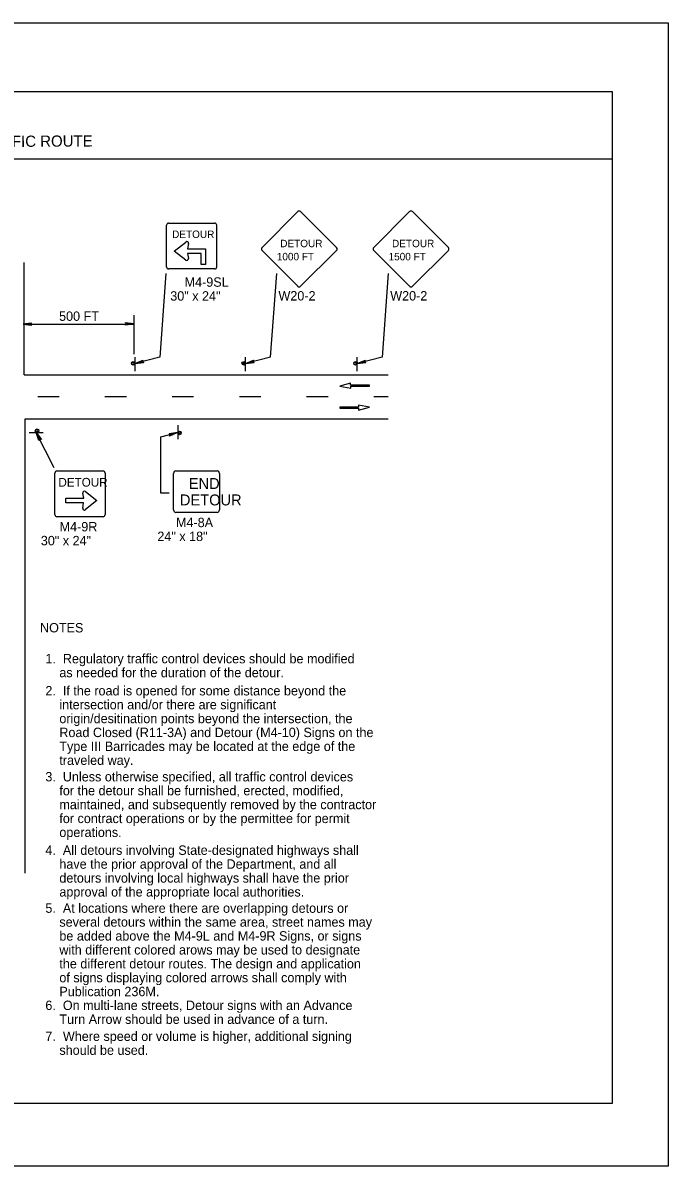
# Model space of a CAD drawing. Extents: x -14145 to -13662, y 30244 to 30661.
# Drawn here: x -13873.57 to -13859.17, y 30262.81 to 30288.31 of the extents above; entities that cross this region are included whole.
import ezdxf

# ---------------------------------------------------------------- set-up
doc = ezdxf.new("R2010")
doc.units = 0
for name, color, linetype in [('1', 7, 'Continuous'), ('10', 7, 'Continuous'), ('2', 7, 'Continuous'), ('4', 7, 'Continuous'), ('61', 7, 'Continuous')]:
    doc.layers.add(name, color=color, linetype=linetype)

msp = doc.modelspace()

# ---------------------------------------------------------------- linework, layer by layer
at = {"layer": '1'}
for p, q in [((-13867.44, 30284.096), (-13868.235, 30283.293)), ((-13866.571, 30283.293), (-13867.374, 30284.096)), ((-13864.946, 30284.096), (-13865.741, 30283.293)), ((-13864.077, 30283.293), (-13864.88, 30284.096)), ((-13870.324, 30283.842), (-13869.291, 30283.842)), ((-13870.367, 30282.866), (-13870.367, 30283.792)), ((-13869.248, 30283.792), (-13869.248, 30282.866)), ((-13870.193, 30283.215), (-13869.936, 30283.418)), ((-13869.875, 30283.382), (-13869.895, 30283.268)), ((-13869.939, 30283.015), (-13870.193, 30283.215)), ((-13869.896, 30283.161), (-13869.877, 30283.049)), ((-13869.597, 30283.161), (-13869.896, 30283.161)), ((-13869.895, 30283.268), (-13869.495, 30283.268)), ((-13869.597, 30282.915), (-13869.597, 30283.163)), ((-13869.495, 30283.268), (-13869.495, 30282.915)), ((-13868.235, 30283.227), (-13867.44, 30282.432)), ((-13867.374, 30282.432), (-13866.571, 30283.227)), ((-13865.741, 30283.227), (-13864.946, 30282.432)), ((-13864.88, 30282.432), (-13864.077, 30283.227)), ((-13873.543, 30280.459), (-13873.543, 30282.96)), ((-13869.291, 30282.817), (-13870.324, 30282.817)), ((-13869.495, 30282.915), (-13869.597, 30282.915)), ((-13870.38, 30282.718), (-13870.517, 30280.847)), ((-13867.914, 30282.718), (-13868.051, 30280.847)), ((-13865.42, 30282.718), (-13865.557, 30280.847)), ((-13871.099, 30281.789), (-13871.099, 30280.915)), ((-13873.565, 30281.585), (-13871.099, 30281.585)), ((-13871.069, 30280.54), (-13871.069, 30280.852)), ((-13871.069, 30280.54), (-13871.069, 30280.852)), ((-13870.516, 30280.847), (-13871.063, 30280.707)), ((-13868.603, 30280.54), (-13868.603, 30280.852)), ((-13868.603, 30280.54), (-13868.603, 30280.852)), ((-13868.05, 30280.847), (-13868.597, 30280.707)), ((-13866.109, 30280.54), (-13866.109, 30280.852)), ((-13866.109, 30280.54), (-13866.109, 30280.852)), ((-13865.556, 30280.847), (-13866.103, 30280.707)), ((-13873.543, 30280.459), (-13865.423, 30280.459)), ((-13866.258, 30280.271), (-13866.499, 30280.205)), ((-13866.258, 30280.226), (-13866.258, 30280.271)), ((-13866.499, 30280.205), (-13866.255, 30280.159)), ((-13865.841, 30280.226), (-13866.258, 30280.226)), ((-13866.255, 30280.159), (-13866.255, 30280.204)), ((-13866.255, 30280.204), (-13865.841, 30280.204)), ((-13865.841, 30280.204), (-13865.841, 30280.226)), ((-13872.761, 30279.968), (-13873.241, 30279.968)), ((-13871.261, 30279.968), (-13871.741, 30279.968)), ((-13869.761, 30279.968), (-13870.241, 30279.968)), ((-13868.261, 30279.968), (-13868.741, 30279.968)), ((-13866.761, 30279.968), (-13867.241, 30279.968)), ((-13866.085, 30279.735), (-13866.499, 30279.735)), ((-13866.499, 30279.735), (-13866.499, 30279.713)), ((-13865.841, 30279.734), (-13866.085, 30279.78)), ((-13866.085, 30279.78), (-13866.085, 30279.735)), ((-13866.083, 30279.668), (-13865.841, 30279.734)), ((-13865.423, 30279.968), (-13865.741, 30279.968)), ((-13873.52, 30279.475), (-13865.423, 30279.475)), ((-13873.52, 30269.341), (-13873.52, 30279.475)), ((-13866.499, 30279.713), (-13866.083, 30279.713)), ((-13866.083, 30279.713), (-13866.083, 30279.668)), ((-13870.117, 30279.334), (-13870.117, 30279.022)), ((-13870.117, 30279.334), (-13870.117, 30279.022)), ((-13870.117, 30279.334), (-13870.117, 30279.022)), ((-13870.117, 30279.334), (-13870.117, 30279.022)), ((-13870.117, 30279.334), (-13870.117, 30279.022)), ((-13870.117, 30279.334), (-13870.117, 30279.022)), ((-13873.428, 30279.17), (-13873.116, 30279.17)), ((-13873.428, 30279.17), (-13873.116, 30279.17)), ((-13873.428, 30279.17), (-13873.116, 30279.17)), ((-13873.428, 30279.17), (-13873.116, 30279.17)), ((-13873.428, 30279.17), (-13873.116, 30279.17)), ((-13873.428, 30279.17), (-13873.116, 30279.17)), ((-13872.876, 30278.384), (-13873.272, 30279.17)), ((-13870.498, 30279.072), (-13870.498, 30277.828)), ((-13870.497, 30279.071), (-13870.123, 30279.167)), ((-13872.856, 30277.34), (-13872.856, 30278.266)), ((-13872.813, 30278.316), (-13871.78, 30278.316)), ((-13871.737, 30278.266), (-13871.737, 30277.34)), ((-13870.21, 30277.447), (-13870.21, 30278.254)), ((-13870.16, 30278.314), (-13869.234, 30278.314)), ((-13869.185, 30278.254), (-13869.185, 30277.447)), ((-13872.616, 30277.6), (-13872.616, 30277.707)), ((-13872.616, 30277.707), (-13872.215, 30277.707)), ((-13872.215, 30277.707), (-13872.234, 30277.819)), ((-13872.172, 30277.853), (-13871.918, 30277.653)), ((-13870.498, 30277.828), (-13870.304, 30277.828)), ((-13872.216, 30277.6), (-13872.616, 30277.6)), ((-13872.236, 30277.486), (-13872.216, 30277.6)), ((-13871.918, 30277.653), (-13872.175, 30277.45)), ((-13871.78, 30277.291), (-13872.813, 30277.291)), ((-13869.234, 30277.386), (-13870.16, 30277.386))]:
    msp.add_line(p, q, dxfattribs=at)
for points in [[(-13873.385, 30281.561), (-13873.391, 30281.579), (-13873.565, 30281.585), (-13873.385, 30281.561), (-13873.379, 30281.555), (-13873.565, 30281.585), (-13873.391, 30281.591), (-13873.385, 30281.609), (-13873.565, 30281.585), (-13873.379, 30281.615), (-13873.385, 30281.609)], [(-13871.279, 30281.615), (-13871.273, 30281.603), (-13871.099, 30281.591), (-13871.279, 30281.615), (-13871.285, 30281.621), (-13871.099, 30281.591), (-13871.273, 30281.585), (-13871.279, 30281.573), (-13871.099, 30281.591), (-13871.285, 30281.561), (-13871.279, 30281.573)], [(-13870.883, 30280.731), (-13870.895, 30280.743), (-13871.063, 30280.707), (-13870.883, 30280.731), (-13870.877, 30280.725), (-13871.063, 30280.707), (-13870.901, 30280.761), (-13870.895, 30280.773), (-13871.063, 30280.707), (-13870.889, 30280.785), (-13870.895, 30280.773)], [(-13868.417, 30280.731), (-13868.429, 30280.743), (-13868.597, 30280.707), (-13868.417, 30280.731), (-13868.411, 30280.725), (-13868.597, 30280.707), (-13868.435, 30280.761), (-13868.429, 30280.773), (-13868.597, 30280.707), (-13868.423, 30280.785), (-13868.429, 30280.773)], [(-13865.923, 30280.731), (-13865.935, 30280.743), (-13866.103, 30280.707), (-13865.923, 30280.731), (-13865.917, 30280.725), (-13866.103, 30280.707), (-13865.941, 30280.761), (-13865.935, 30280.773), (-13866.103, 30280.707), (-13865.929, 30280.785), (-13865.935, 30280.773)], [(-13873.21, 30278.999), (-13873.201, 30279.014), (-13873.272, 30279.17), (-13873.21, 30278.999), (-13873.215, 30278.992), (-13873.272, 30279.17), (-13873.185, 30279.023), (-13873.172, 30279.02), (-13873.272, 30279.17), (-13873.159, 30279.017), (-13873.172, 30279.02)], [(-13873.21, 30278.999), (-13873.201, 30279.014), (-13873.272, 30279.17), (-13873.21, 30278.999), (-13873.215, 30278.992), (-13873.272, 30279.17), (-13873.185, 30279.023), (-13873.172, 30279.02), (-13873.272, 30279.17), (-13873.159, 30279.017), (-13873.172, 30279.02)], [(-13873.21, 30278.999), (-13873.201, 30279.014), (-13873.272, 30279.17), (-13873.21, 30278.999), (-13873.215, 30278.992), (-13873.272, 30279.17), (-13873.185, 30279.023), (-13873.172, 30279.02), (-13873.272, 30279.17), (-13873.159, 30279.017), (-13873.172, 30279.02)], [(-13870.303, 30279.143), (-13870.291, 30279.131), (-13870.123, 30279.167), (-13870.303, 30279.143), (-13870.309, 30279.149), (-13870.123, 30279.167), (-13870.285, 30279.113), (-13870.291, 30279.101), (-13870.123, 30279.167), (-13870.297, 30279.089), (-13870.291, 30279.101)]]:
    msp.add_lwpolyline(points, dxfattribs=at)
for centre in [(-13871.109, 30280.713), (-13868.643, 30280.713), (-13866.149, 30280.713), (-13873.254, 30279.211), (-13873.254, 30279.211), (-13873.254, 30279.211), (-13870.077, 30279.161), (-13870.077, 30279.161), (-13870.077, 30279.161)]:
    msp.add_circle(centre, 0.0408, dxfattribs=at)
for centre, radius, start, end in [((-13867.408, 30284.063), 0.0465, 45, 135), ((-13864.914, 30284.063), 0.0465, 45, 135), ((-13869.913, 30283.389), 0.038, 348.2476, 132.1543), ((-13868.203, 30283.261), 0.0465, 135, 225), ((-13866.605, 30283.26), 0.0465, 315, 45), ((-13865.709, 30283.261), 0.0465, 135, 225), ((-13864.111, 30283.26), 0.0465, 315, 45), ((-13869.915, 30283.045), 0.038, 229.8591, 10.5247), ((-13867.408, 30282.465), 0.0465, 225, 315), ((-13864.914, 30282.465), 0.0465, 225, 315), ((-13871.104, 30280.705), 0.0214, 9.521, 4.2501), ((-13868.638, 30280.705), 0.0214, 9.521, 4.2501), ((-13866.144, 30280.705), 0.0214, 9.521, 4.2501), ((-13873.262, 30279.206), 0.0214, 279.521, 274.2501), ((-13873.262, 30279.206), 0.0214, 279.521, 274.2501), ((-13873.262, 30279.206), 0.0214, 279.521, 274.2501), ((-13870.082, 30279.169), 0.0214, 189.521, 184.2501), ((-13870.082, 30279.169), 0.0214, 189.521, 184.2501), ((-13870.082, 30279.169), 0.0214, 189.521, 184.2501), ((-13872.198, 30277.823), 0.038, 49.8591, 190.5247), ((-13872.2, 30277.479), 0.038, 168.2476, 312.1543)]:
    msp.add_arc(centre, radius, start, end, dxfattribs=at)
for centre, major_axis, ratio, start_param, end_param in [((-13870.324, 30283.792), (0, -0.0492), 0.866667, 3.141593, 4.712389), ((-13869.29, 30283.792), (0, 0.0492), 0.866667, 4.712389, 6.283185), ((-13870.324, 30282.865), (0, -0.0492), 0.866667, 4.712389, 6.283185), ((-13869.29, 30282.865), (0, 0.0492), 0.866667, 3.141593, 4.712389), ((-13872.813, 30278.266), (0, -0.0492), 0.866667, 3.141593, 4.712389), ((-13871.78, 30278.266), (0, 0.0492), 0.866667, 4.712389, 6.283185), ((-13870.161, 30278.254), (0, -0.0602), 0.817773, 3.141593, 4.712389), ((-13869.235, 30278.254), (0, 0.0602), 0.817773, 4.712389, 6.283185), ((-13870.161, 30277.447), (0, -0.0602), 0.817773, 4.712389, 6.283185), ((-13869.235, 30277.447), (0, 0.0602), 0.817773, 3.141593, 4.712389), ((-13872.813, 30277.339), (0, -0.0492), 0.866667, 4.712389, 6.283185), ((-13871.78, 30277.339), (0, 0.0492), 0.866667, 3.141593, 4.712389)]:
    msp.add_ellipse(centre, major_axis=major_axis, ratio=ratio, start_param=start_param, end_param=end_param, dxfattribs=at)
at = {"layer": '10'}
for p, q in [((-13891.874, 30286.777), (-13860.422, 30286.777)), ((-13860.422, 30286.777), (-13860.422, 30264.207)), ((-13891.874, 30285.277), (-13860.422, 30285.277)), ((-13860.422, 30264.207), (-13891.874, 30264.207))]:
    msp.add_line(p, q, dxfattribs=at)
at = {"layer": '61'}
msp.add_lwpolyline([(-13892.174, 30288.307), (-13859.174, 30288.307), (-13859.174, 30262.807), (-13892.174, 30262.807)], close=True, dxfattribs=at)

# ---------------------------------------------------------------- texts
at = {"layer": '1'}
for s, height, p in [('DETOUR', 0.1669, (-13870.242, 30283.508)), ('DETOUR', 0.1669, (-13867.829, 30283.303)), ('DETOUR', 0.1669, (-13865.335, 30283.303)), ('1000 FT', 0.1669, (-13867.906, 30283.01)), ('1500 FT', 0.1669, (-13865.412, 30283.01)), ('DETOUR', 0.1941, (-13872.778, 30277.963)), ('END', 0.244, (-13869.87, 30277.91)), ('DETOUR', 0.244, (-13870.068, 30277.544))]:
    msp.add_text(s, height=height, dxfattribs=at).set_placement(p)
at = {"layer": '2'}
for s, p in [('M4-9SL', (-13869.963, 30282.421)), ('30" x 24"', (-13870.283, 30282.111)), ('W20-2', (-13867.869, 30282.114)), ('W20-2', (-13865.375, 30282.114)), ('500 FT', (-13872.764, 30281.66)), ('M4-9R', (-13872.752, 30276.964)), ('M4-8A', (-13870.155, 30277.059)), ('24" x 18"', (-13870.571, 30276.749)), ('30" x 24"', (-13873.171, 30276.654)), ('NOTES', (-13873.189, 30274.711)), ('1.  Regulatory traffic control devices should be modified ', (-13873.07, 30274.021)), ('    as needed for the duration of the detour.', (-13873.07, 30273.711)), ('2.  If the road is opened for some distance beyond the', (-13873.07, 30273.306)), ('    intersection and/or there are significant', (-13873.07, 30272.996)), ('    origin/desitination points beyond the intersection, the', (-13873.07, 30272.686)), ('    Road Closed (R11-3A) and Detour (M4-10) Signs on the', (-13873.07, 30272.376)), ('    Type III Barricades may be located at the edge of the', (-13873.07, 30272.066)), ('    traveled way.', (-13873.07, 30271.756)), ('3.  Unless otherwise specified, all traffic control devices', (-13873.07, 30271.388)), ('    for the detour shall be furnished, erected, modified,', (-13873.07, 30271.078)), ('    maintained, and subsequently removed by the contractor', (-13873.07, 30270.768)), ('    for contract operations or by the permittee for permit', (-13873.07, 30270.458)), ('    operations.', (-13873.07, 30270.148)), ('4.  All detours involving State-designated highways shall', (-13873.07, 30269.75)), ('    have the prior approval of the Department, and all', (-13873.07, 30269.44)), ('    detours involving local highways shall have the prior', (-13873.07, 30269.13)), ('    approval of the appropriate local authorities.', (-13873.07, 30268.82)), ('5.  At locations where there are overlapping detours or', (-13873.07, 30268.457)), ('    several detours within the same area, street names may ', (-13873.07, 30268.147)), ('    be added above the M4-9L and M4-9R Signs, or signs', (-13873.07, 30267.837)), ('    with different colored arows may be used to designate', (-13873.07, 30267.527)), ('    the different detour routes. The design and application ', (-13873.07, 30267.217)), ('    of signs displaying colored arrows shall comply with', (-13873.07, 30266.907)), ('    Publication 236M.', (-13873.07, 30266.597)), ('6.  On multi-lane streets, Detour signs with an Advance ', (-13873.07, 30266.289)), ('    Turn Arrow should be used in advance of a turn.', (-13873.07, 30265.979)), ('7.  Where speed or volume is higher, additional signing', (-13873.069, 30265.599)), ('    should be used.', (-13873.069, 30265.289))]:
    msp.add_text(s, height=0.21, dxfattribs=at).set_placement(p)
at = {"layer": '4'}
msp.add_text('ANY HIGHWAY - DETOUR OF AN UNNUMBERED TRAFFIC ROUTE', height=0.25, rotation=0.31, dxfattribs=at).set_placement((-13882.471, 30285.493))

doc.saveas('drawing.dxf')
